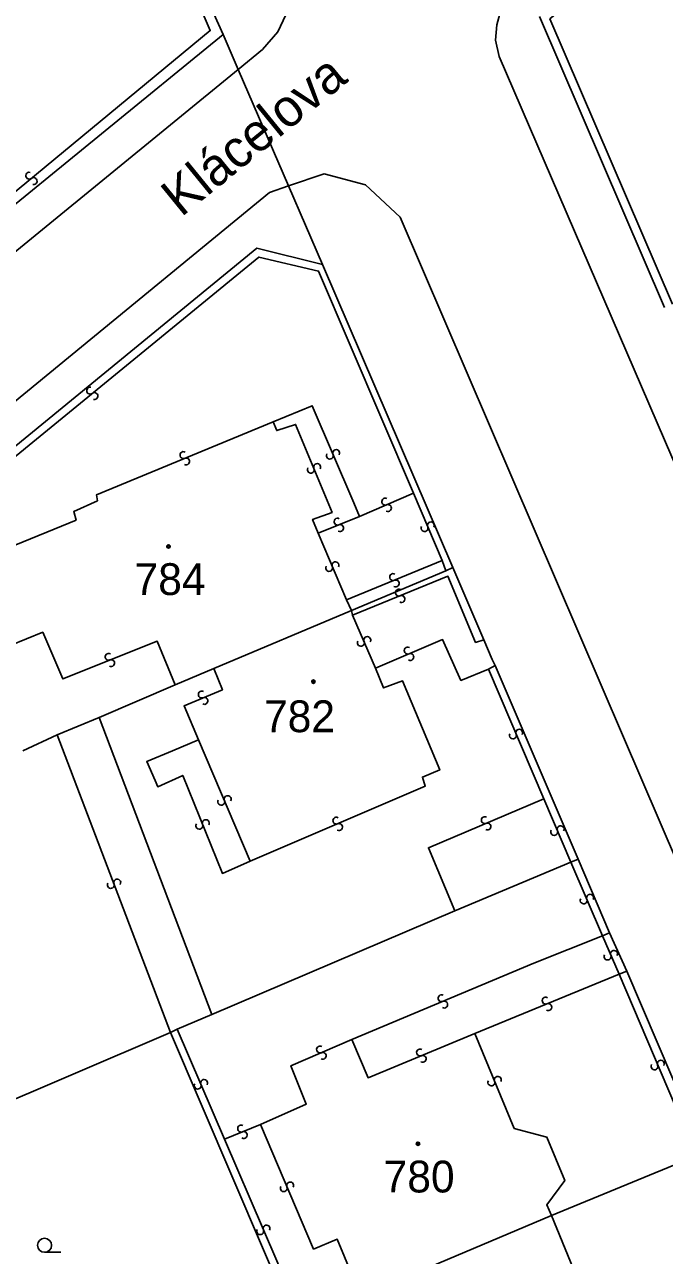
# Model space of a CAD drawing. Extents: x -600391 to -599491, y -1160176 to -1159402.
# Drawn here: x -599989.8 to -599955.6, y -1160026.6 to -1159960.8 of the extents above; entities that cross this region are included whole.
import ezdxf

# ---------------------------------------------------------------- set-up
doc = ezdxf.new("R2010")
doc.units = 0
for name, color, linetype in [('Level 1', 7, 'Continuous'), ('Level 11', 7, 'Continuous'), ('Level 13', 7, 'Continuous'), ('Level 3', 7, 'Continuous'), ('Level 4', 7, 'Continuous'), ('Level 5', 7, 'Continuous')]:
    doc.layers.add(name, color=color, linetype=linetype)

msp = doc.modelspace()

# ---------------------------------------------------------------- linework, layer by layer
at = {"layer": 'Level 1'}
for points in [[(-599982.86, -1159953.19), (-599979.19, -1159961.34)], [(-599955.61, -1159975.93), (-599962.28, -1159960.37)], [(-599998.71, -1159977.25), (-599979.19, -1159961.34)], [(-599978.39, -1159963.2), (-599979.19, -1159961.34)], [(-599975.69, -1159969.42), (-599978.39, -1159963.2)], [(-599975.69, -1159969.42), (-599973.88, -1159973.63)], [(-599995.24, -1159987.38), (-599977.39, -1159972.75), (-599973.88, -1159973.63)], [(-599966.92, -1159989.81), (-599973.88, -1159973.63)], [(-599967.3, -1159990), (-599972.34, -1159992.12)], [(-599966.92, -1159989.81), (-599967.3, -1159990)], [(-599965.26, -1159993.68), (-599966.92, -1159989.81)], [(-599972.34, -1159992.12), (-599979.69, -1159995.21)], [(-599964.65, -1159995.05), (-599964.81, -1159994.73), (-599965.26, -1159993.68)], [(-599979.69, -1159995.21), (-599981.76, -1159996.09)], [(-599960.23, -1160005.4), (-599964.65, -1159995.05)], [(-599981.76, -1159996.09), (-599985.82, -1159997.84)], [(-599985.82, -1159997.84), (-599988.05, -1159998.76)], [(-599979.8, -1160013.71), (-599985.82, -1159997.84)], [(-599988.05, -1159998.76), (-599989.9, -1159999.62)], [(-599960.61, -1160005.57), (-599966.81, -1160008.17)], [(-599960.23, -1160005.4), (-599960.61, -1160005.57)], [(-599958.55, -1160009.35), (-599960.23, -1160005.4)], [(-599966.81, -1160008.17), (-599979.8, -1160013.71)], [(-599957.62, -1160011.39), (-599958.55, -1160009.35)], [(-599953.5, -1160021.06), (-599957.62, -1160011.39)], [(-599979.8, -1160013.71), (-599981.64, -1160014.5)], [(-599982, -1160014.68), (-599992.3, -1160019.08), (-600000.82, -1160026.5)], [(-599981.64, -1160014.5), (-599982, -1160014.68)], [(-599975.35, -1160030.25), (-599982, -1160014.68)], [(-599953.91, -1160021.26), (-599961.64, -1160024.45)], [(-599961.64, -1160024.45), (-599971.83, -1160028.76)]]:
    msp.add_lwpolyline(points, dxfattribs=at)
at = {"layer": 'Level 13'}
for centre, start, end in [((-599989.547, -1159968.878), 76.73887, 309.32887), ((-599989.314, -1159969.163), 256.95333, 129.05132), ((-599986.296, -1159980.367), 76.45645, 309.04645), ((-599986.065, -1159980.654), 256.67091, 128.76891), ((-599973.15, -1159983.699), 330.58462, 202.68262), ((-599981.309, -1159983.809), 59.85038, 291.94838), ((-599981.17, -1159984.15), 239.63593, 112.22593), ((-599973.489, -1159983.842), 150.37016, 22.96016), ((-599974.51, -1159984.59), 149.69153, 22.28153), ((-599974.169, -1159984.451), 329.90598, 202.00398), ((-599970.532, -1159986.3), 61.00211, 293.10011), ((-599970.387, -1159986.639), 240.78766, 113.37766), ((-599973.078, -1159987.369), 59.00417, 291.59417), ((-599968.09, -1159987.569), 330.12661, 202.71661), ((-599972.943, -1159987.712), 239.21863, 111.31663), ((-599968.43, -1159987.71), 150.34107, 22.43906), ((-599973.53, -1159989.842), 150.27913, 22.86913), ((-599973.19, -1159989.699), 330.49358, 202.59158), ((-599970.109, -1159990.329), 59.71338, 291.81138), ((-599969.971, -1159990.671), 239.49892, 112.08893), ((-599969.798, -1159991.158), 59.4641, 291.5621), ((-599969.662, -1159991.501), 239.24964, 111.83964), ((-599971.829, -1159993.843), 150.64944, 23.23944), ((-599971.49, -1159993.698), 330.86389, 202.96189), ((-599969.331, -1159994.26), 60.16343, 292.75343), ((-599985.308, -1159994.589), 59.0382, 291.6282), ((-599985.173, -1159994.932), 239.25266, 111.35066), ((-599969.189, -1159994.6), 240.37789, 112.47589), ((-599980.33, -1159996.609), 60.13138, 292.22938), ((-599980.19, -1159996.95), 239.91692, 112.50692), ((-599963.71, -1159998.791), 150.60129, 22.69929), ((-599963.371, -1159998.648), 330.38684, 202.97684), ((-599979.29, -1160002.34), 150.33651, 22.4345), ((-599978.95, -1160002.199), 330.12205, 202.71205), ((-599980.119, -1160003.482), 329.18556, 201.77556), ((-599973.142, -1160003.35), 60.34948, 292.93948), ((-599965.211, -1160003.32), 60.16607, 292.75607), ((-599980.462, -1160003.618), 149.40001, 21.49801), ((-599972.999, -1160003.69), 240.56394, 112.66193), ((-599965.069, -1160003.66), 240.38053, 112.47852), ((-599961.5, -1160003.951), 150.38749, 22.48548), ((-599961.16, -1160003.809), 330.17303, 202.76303), ((-599984.847, -1160006.656), 328.18078, 200.27878), ((-599985.192, -1160006.785), 147.96633, 20.55633), ((-599959.929, -1160007.612), 150.37442, 22.96442), ((-599959.59, -1160007.469), 330.58887, 202.68687), ((-599958.649, -1160010.612), 150.39059, 22.98059), ((-599958.31, -1160010.469), 330.60505, 202.70304), ((-599967.52, -1160012.839), 60.14311, 292.24111), ((-599967.38, -1160013.18), 239.92866, 112.51866), ((-599961.959, -1160012.969), 59.74913, 291.84712), ((-599961.821, -1160013.311), 239.53467, 112.12467), ((-599974.011, -1160015.58), 60.61373, 292.71173), ((-599973.868, -1160015.919), 240.39928, 112.98928), ((-599968.669, -1160015.739), 59.82853, 291.92653), ((-599968.53, -1160016.08), 239.61407, 112.20408), ((-599956.15, -1160016.481), 150.22128, 22.81128), ((-599955.81, -1160016.339), 330.43574, 202.53374), ((-599964.519, -1160017.201), 329.87213, 201.97013), ((-599980.549, -1160017.512), 150.3922, 22.9822), ((-599980.21, -1160017.369), 330.60666, 202.70465), ((-599964.86, -1160017.34), 149.65767, 22.24767), ((-599978.228, -1160019.808), 59.48218, 291.58018), ((-599978.091, -1160020.151), 239.26773, 111.85773), ((-599975.95, -1160022.991), 150.46741, 22.56541), ((-599975.61, -1160022.849), 330.25296, 202.84296), ((-599976.87, -1160025.149), 330.63545, 202.73345), ((-599977.209, -1160025.292), 150.421, 23.011)]:
    msp.add_arc(centre, 0.184, start, end, dxfattribs=at)
at = {"layer": 'Level 3'}
for points in [[(-599978.39, -1159963.2), (-599977.09, -1159962.14), (-599976.27, -1159961.19), (-599975.7, -1159959.98), (-599975.49, -1159959.08), (-599975.52, -1159957.88), (-599975.83, -1159956.72), (-599987.06, -1159931.18), (-599993.24, -1159917.86), (-600001.54, -1159900.55), (-600011.9, -1159880.23), (-600040.56, -1159827.59)], [(-599955.18, -1159975.74), (-599961.73, -1159960.5), (-599938.86, -1159941.7)], [(-599982.86, -1159953.19), (-599983.21, -1159953.35), (-599979.88, -1159961.12), (-599998.98, -1159976.91)], [(-599916.7, -1160066.63), (-599917.11, -1160066.76), (-599917.67, -1160067), (-599918.32, -1160067.07), (-599918.8, -1160066.99), (-599919.27, -1160066.8), (-599919.69, -1160066.51), (-599919.99, -1160066.19), (-599936.81, -1160026.95), (-599950.41, -1159995.05), (-599964.44, -1159962.51), (-599964.64, -1159961.64), (-599964.57, -1159960.81), (-599964.41, -1159960.23), (-599964.11, -1159959.66), (-599963.69, -1159959.11), (-599963.03, -1159958.57)], [(-599978.39, -1159963.2), (-600017, -1159994.77), (-600057.77, -1160028.11), (-600058.2, -1160028.15)], [(-599932.07, -1160071.24), (-599930.91, -1160071.01), (-599929.76, -1160070.79), (-599929.09, -1160070.48), (-599928.67, -1160069.97), (-599928.31, -1160069.23), (-599928.2, -1160068.62), (-599928.16, -1160067.74), (-599944.31, -1160030.32), (-599957.81, -1159998.89), (-599969.74, -1159971.09), (-599971.59, -1159969.36), (-599973.79, -1159968.78), (-599975.69, -1159969.42)], [(-600055.38, -1160034.38), (-599976.71, -1159969.77), (-599975.69, -1159969.42)], [(-599969.02, -1159985.84), (-599974.09, -1159973.98), (-599977.28, -1159973.23), (-599995.07, -1159987.79)], [(-599976.51, -1159982.03), (-599974.43, -1159981.17), (-599972.2, -1159986.37), (-599971.9, -1159987.1)], [(-599992.33, -1159990), (-599990.49, -1159989.26), (-599990.66, -1159988.77), (-599987.05, -1159987.28), (-599987.17, -1159986.83), (-599985.91, -1159986.25), (-599985.96, -1159985.94), (-599976.51, -1159982.03)], [(-599976.51, -1159982.03), (-599976.33, -1159982.5), (-599975.32, -1159982.17), (-599973.37, -1159986.87), (-599974.41, -1159987.25), (-599974.12, -1159987.99)], [(-599971.9, -1159987.1), (-599969.02, -1159985.84)], [(-599967.49, -1159989.45), (-599969.02, -1159985.84)], [(-599971.9, -1159987.1), (-599974.12, -1159987.99)], [(-599974.12, -1159987.99), (-599972.6, -1159991.55)], [(-599972.6, -1159991.55), (-599967.49, -1159989.45)], [(-599967.49, -1159989.45), (-599967.3, -1159990)], [(-599981.76, -1159996.09), (-599982.72, -1159993.75), (-599987.75, -1159995.77), (-599988.83, -1159993.28), (-599990.56, -1159993.99), (-599992.33, -1159990)], [(-599972.28, -1159992.36), (-599967.18, -1159990.29), (-599965.7, -1159993.82), (-599965.26, -1159993.68)], [(-599972.6, -1159991.55), (-599972.34, -1159992.12)], [(-599972.34, -1159992.12), (-599972.28, -1159992.36)], [(-599972.28, -1159992.36), (-599971.05, -1159995.19)], [(-599965.02, -1159995.26), (-599966.49, -1159995.85), (-599967.47, -1159993.67), (-599971.05, -1159995.19)], [(-599980.5, -1159999.03), (-599981.28, -1159997.21), (-599979.23, -1159996.35), (-599979.69, -1159995.21)], [(-599971.05, -1159995.19), (-599970.62, -1159996.25), (-599969.6, -1159995.88), (-599967.62, -1160000.64), (-599968.54, -1160001.02), (-599968.39, -1160001.51), (-599977.75, -1160005.52)], [(-599965.02, -1159995.26), (-599964.65, -1159995.05)], [(-599962.05, -1160002.18), (-599965.02, -1159995.26)], [(-599988.05, -1159998.76), (-599982, -1160014.68)], [(-599977.75, -1160005.52), (-599979.23, -1160006.17), (-599981.35, -1160000.93), (-599982.68, -1160001.54), (-599982.82, -1160001.21), (-599983.27, -1160000.19), (-599981.89, -1159999.61), (-599980.5, -1159999.03)], [(-599977.75, -1160005.52), (-599980.5, -1159999.03)], [(-599962.05, -1160002.18), (-599968.22, -1160004.8), (-599966.81, -1160008.17)], [(-599960.61, -1160005.57), (-599962.05, -1160002.18)], [(-599960.61, -1160005.57), (-599958.92, -1160009.51)], [(-599972.31, -1160015.05), (-599962.59, -1160010.97), (-599958.92, -1160009.51)], [(-599958.92, -1160009.51), (-599958.55, -1160009.35)], [(-599958.92, -1160009.51), (-599958.04, -1160011.56)], [(-599965.74, -1160014.73), (-599958.04, -1160011.56)], [(-599958.04, -1160011.56), (-599957.62, -1160011.39)], [(-599958.04, -1160011.56), (-599953.91, -1160021.26)], [(-599981.64, -1160014.5), (-599979.12, -1160020.37)], [(-599977.2, -1160019.59), (-599974.75, -1160018.5), (-599975.57, -1160016.45), (-599972.31, -1160015.05)], [(-599972.31, -1160015.05), (-599971.45, -1160017.09), (-599965.74, -1160014.73)], [(-599965.74, -1160014.73), (-599963.64, -1160019.8), (-599961.89, -1160020.27), (-599960.94, -1160022.58), (-599961.9, -1160023.89), (-599961.64, -1160024.45)], [(-599979.12, -1160020.37), (-599977.2, -1160019.59)], [(-599971.83, -1160028.76), (-599973.09, -1160025.72), (-599974.36, -1160026.25), (-599977.2, -1160019.59)], [(-599979.12, -1160020.37), (-599974.95, -1160030.07)], [(-599961.64, -1160024.45), (-599959.61, -1160029.4), (-599960.78, -1160029.93), (-599959.35, -1160033.41)]]:
    msp.add_lwpolyline(points, dxfattribs=at)
at = {"layer": 'Level 5'}
msp.add_line((-599988.73, -1160026.42), (-599987.855, -1160026.42), dxfattribs=at)
for centre, radius in [((-599982.11, -1159988.69), 0.09), ((-599982.11, -1159988.69), 0.0521), ((-599974.37, -1159995.92), 0.09), ((-599974.37, -1159995.92), 0.0521), ((-599968.78, -1160020.62), 0.09), ((-599968.78, -1160020.62), 0.0521), ((-599988.73, -1160026.045), 0.375)]:
    msp.add_circle(centre, radius, dxfattribs=at)

# ---------------------------------------------------------------- texts
at = {"layer": 'Level 11'}
msp.add_text('Klácelova', height=2, rotation=39.17825, dxfattribs=at).set_placement((-599981.437, -1159971.128))
at = {"layer": 'Level 4'}
for s, p in [('784', (-599983.922, -1159991.29)), ('782', (-599977.007, -1159998.62)), ('780', (-599970.616, -1160023.22))]:
    msp.add_text(s, height=1.7, dxfattribs=at).set_placement(p)

doc.saveas('drawing.dxf')
